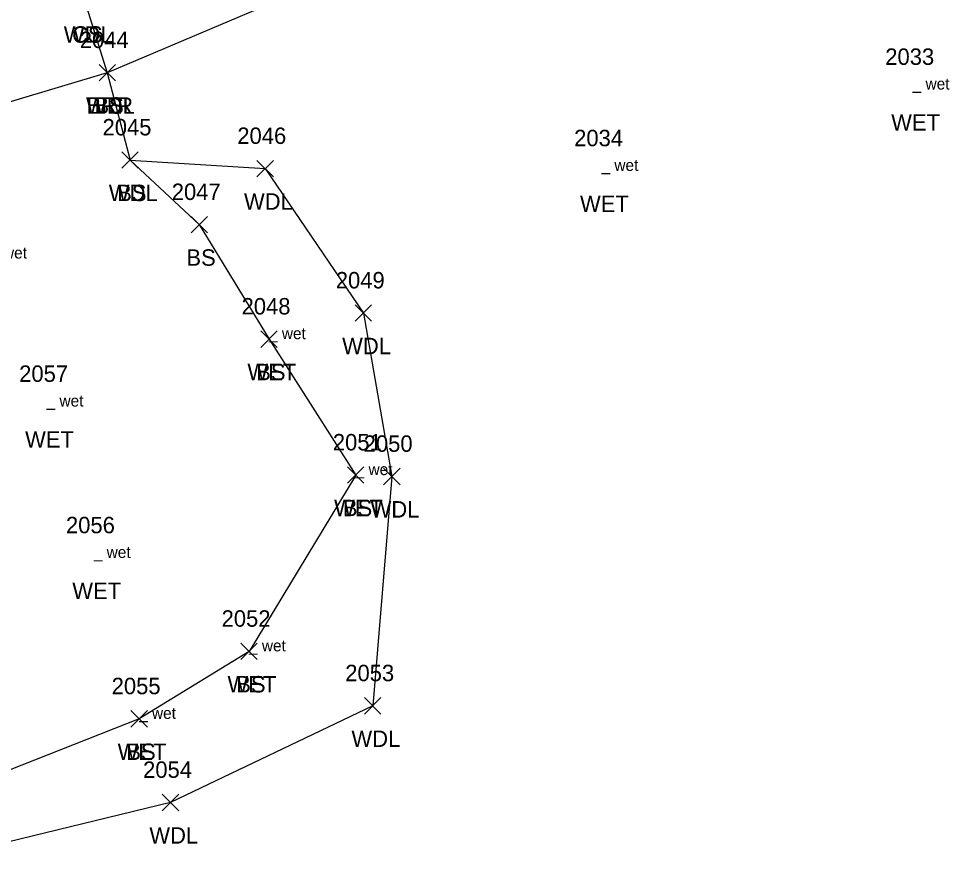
# Model space of a CAD drawing. Extents: x 1502194 to 1507887, y 142265 to 144150.
# Drawn here: x 1506840 to 1506953.2, y 143368.6 to 143470.6 of the extents above; entities that cross this region are included whole.
import ezdxf

# ---------------------------------------------------------------- set-up
doc = ezdxf.new("R2010")
doc.units = 0
for name, color, linetype in [('L_A', 7, 'Continuous'), ('L_I', 7, 'Continuous'), ('L_TIC', 7, 'Continuous'), ('LABL', 7, 'Continuous'), ('LAWA', 7, 'Continuous'), ('LELB', 7, 'Continuous'), ('LWET', 7, 'Continuous')]:
    doc.layers.add(name, color=color, linetype=linetype)

msp = doc.modelspace()

# ---------------------------------------------------------------- linework, layer by layer
at = {"layer": 'L_TIC'}
for points in [[(1506849.82, 143463.05), (1506851.82, 143465.05)], [(1506851.82, 143463.05), (1506849.82, 143465.05)], [(1506849.82, 143463.05), (1506851.82, 143465.05)], [(1506851.82, 143463.05), (1506849.82, 143465.05)], [(1506849.82, 143463.05), (1506851.82, 143465.05)], [(1506851.82, 143463.05), (1506849.82, 143465.05)], [(1506852.59, 143452.42), (1506854.59, 143454.42)], [(1506854.59, 143452.42), (1506852.59, 143454.42)], [(1506852.59, 143452.42), (1506854.59, 143454.42)], [(1506854.59, 143452.42), (1506852.59, 143454.42)], [(1506869.03, 143451.38), (1506871.03, 143453.38)], [(1506871.03, 143451.38), (1506869.03, 143453.38)], [(1506861.01, 143444.56), (1506863.01, 143446.56)], [(1506863.01, 143444.56), (1506861.01, 143446.56)], [(1506880.97, 143433.8), (1506882.97, 143435.8)], [(1506882.97, 143433.8), (1506880.97, 143435.8)], [(1506869.5, 143430.63), (1506871.5, 143432.63)], [(1506871.5, 143430.63), (1506869.5, 143432.63)], [(1506880.04, 143414.09), (1506882.04, 143416.09)], [(1506882.04, 143414.09), (1506880.04, 143416.09)], [(1506884.44, 143413.92), (1506886.44, 143415.92)], [(1506886.44, 143413.92), (1506884.44, 143415.92)], [(1506867.07, 143392.64), (1506869.07, 143394.64)], [(1506869.07, 143392.64), (1506867.07, 143394.64)], [(1506882.11, 143386.01), (1506884.11, 143388.01)], [(1506884.11, 143386.01), (1506882.11, 143388.01)], [(1506853.7, 143384.43), (1506855.7, 143386.43)], [(1506855.7, 143384.43), (1506853.7, 143386.43)], [(1506857.52, 143374.25), (1506859.52, 143376.25)], [(1506859.52, 143374.25), (1506857.52, 143376.25)]]:
    msp.add_lwpolyline(points, dxfattribs=at)
at = {"layer": 'LABL'}
msp.add_lwpolyline([(1506850.82, 143464.05), (1506827.75, 143457.15), (1506806.24, 143448.63), (1506776.99, 143440.27), (1506769, 143436.63), (1506724.43, 143433.85), (1506664.3, 143424.7), (1506616.52, 143414.64)], dxfattribs=at)
at = {"layer": 'LAWA'}
msp.add_lwpolyline([(1506932.63, 143515.25), (1506892.28, 143496.29), (1506848.11, 143472.7), (1506850.82, 143464.05), (1506853.59, 143453.42), (1506870.03, 143452.38), (1506881.97, 143434.8), (1506885.44, 143414.92), (1506883.11, 143387.01), (1506858.52, 143375.25), (1506831, 143368.57)], dxfattribs=at)
at = {"layer": 'LELB'}
for points in [[(1506936.48, 143507.25), (1506897.7, 143483.93), (1506850.82, 143464.05)], [(1506853.59, 143453.42), (1506862.01, 143445.56), (1506870.5, 143431.63), (1506881.04, 143415.09), (1506868.07, 143393.64), (1506854.7, 143385.43), (1506834.02, 143377.29), (1506828.29, 143375.32)]]:
    msp.add_lwpolyline(points, dxfattribs=at)

# ---------------------------------------------------------------- texts
at = {"layer": 'L_A'}
for s, p in [('WDL', (1506845.53, 143467.7)), ('CS', (1506846.55, 143467.7)), ('WDL', (1506848.24, 143459.05)), ('BRR', (1506848.31, 143459.05)), ('BS', (1506849.26, 143459.05)), ('WET', (1506946.17, 143457)), ('WDL', (1506851.01, 143448.42)), ('BS', (1506852.03, 143448.42)), ('WDL', (1506867.45, 143447.38)), ('WET', (1506908.32, 143447.1)), ('BS', (1506860.45, 143440.56)), ('WDL', (1506879.39, 143429.8)), ('WET', (1506867.87, 143426.63)), ('BS', (1506868.94, 143426.63)), ('WET', (1506840.83, 143418.43)), ('BS', (1506879.48, 143410.09)), ('WET', (1506878.41, 143410.09)), ('WDL', (1506882.85, 143409.92)), ('WET', (1506846.57, 143400.01)), ('WET', (1506865.45, 143388.64)), ('BS', (1506866.51, 143388.64)), ('WDL', (1506880.52, 143382.01)), ('WET', (1506852.08, 143380.43)), ('BS', (1506853.14, 143380.43)), ('WDL', (1506855.94, 143370.25))]:
    msp.add_text(s, height=2, dxfattribs=at).set_placement(p)
at = {"layer": 'L_I'}
for s, p in [('2044', (1506847.48, 143467.05)), ('2044', (1506847.48, 143467.05)), ('2044', (1506847.48, 143467.05)), ('2033', (1506945.45, 143465)), ('2045', (1506850.25, 143456.42)), ('2045', (1506850.25, 143456.42)), ('2046', (1506866.64, 143455.38)), ('2034', (1506907.61, 143455.1)), ('2047', (1506858.67, 143448.56)), ('2049', (1506878.62, 143437.8)), ('2048', (1506867.16, 143434.63)), ('2048', (1506867.16, 143434.63)), ('2057', (1506840.11, 143426.43)), ('2051', (1506878.26, 143418.09)), ('2051', (1506878.26, 143418.09)), ('2050', (1506882.01, 143417.92)), ('2056', (1506845.8, 143408.01)), ('2052', (1506864.73, 143396.64)), ('2052', (1506864.73, 143396.64)), ('2053', (1506879.77, 143390.01)), ('2055', (1506851.36, 143388.43)), ('2055', (1506851.36, 143388.43)), ('2054', (1506855.18, 143378.25))]:
    msp.add_text(s, height=2, dxfattribs=at).set_placement(p)
at = {"layer": 'LWET'}
for p in [(1506948.79, 143462), (1506910.94, 143452.1), (1506836.58, 143441.44), (1506870.5, 143431.63), (1506843.45, 143423.43), (1506881.04, 143415.09), (1506849.19, 143405.01), (1506868.07, 143393.64), (1506854.7, 143385.43)]:
    msp.add_text('_ wet', height=1.4, dxfattribs=at).set_placement(p)

doc.saveas('drawing.dxf')
